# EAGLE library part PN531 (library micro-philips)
Near Field Communication Transmission module Source: http://www.semiconductors.philips.com/acrobat_download/other/identification/sfs_pn531_rev2.0.pdf
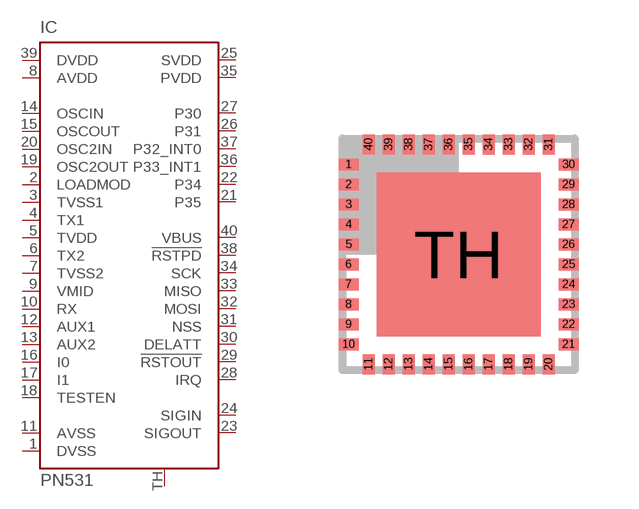
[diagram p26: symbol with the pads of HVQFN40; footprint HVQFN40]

Designator prefix IC

## PN531 (MPN: PN5310A3HN/C203,51; OC_FARNELL: unknown; OC_NEWARK: 70R7886)  [HVQFN40]
1  DVSS  pwr
2  LOADMOD  out
3  TVSS1  pwr
4  TX1  out
5  TVDD  pwr
6  TX2  out
7  TVSS2  pwr
8  AVDD  pwr
9  VMID  pwr
10  RX  in
11  AVSS  pwr
12  AUX1  out
13  AUX2  out
14  OSCIN  in
15  OSCOUT  out
16  I0  in
17  I1  in
18  TESTEN  in
19  OSC2OUT  out
20  OSC2IN  in
21  P35
22  P34
23  SIGOUT  out
24  SIGIN  in
25  SVDD  pwr
26  P31
27  P30
28  IRQ  out
29  !RSTOUT
30  DELATT  out
31  NSS
32  MOSI
33  MISO
34  SCK
35  PVDD  pwr
36  P33_INT1
37  P32_INT0
38  !RSTPD  in
39  DVDD  in
40  VBUS  in
TH  TH  pas

## Footprint HVQFN40 (pad centres in mm)
HVQFN40 plastic thermal enhanced very thin quad flat package SOT618-1 no leads; 40 terminals; body 6 x 6 x 0.85 mm Source: http://www.semiconductors.philips.com/acrobat_download/packages/SOT618-1.pdf
smd 0.5 x 0.3: 1 -2.75,2.25; 2 -2.75,1.75; 3 -2.75,1.25; 4 -2.75,0.75; 5 -2.75,0.25; 6 -2.75,-0.25; 7 -2.75,-0.75; 8 -2.75,-1.25; 9 -2.75,-1.75; 10 -2.75,-2.25; 21 2.75,-2.25; 22 2.75,-1.75; 23 2.75,-1.25; 24 2.75,-0.75; 25 2.75,-0.25; 26 2.75,0.25; 27 2.75,0.75; 28 2.75,1.25; 29 2.75,1.75; 30 2.75,2.25
smd 0.3 x 0.5: 11 -2.25,-2.75; 12 -1.75,-2.75; 13 -1.25,-2.75; 14 -0.75,-2.75; 15 -0.25,-2.75; 16 0.25,-2.75; 17 0.75,-2.75; 18 1.25,-2.75; 19 1.75,-2.75; 20 2.25,-2.75; 31 2.25,2.75; 32 1.75,2.75; 33 1.25,2.75; 34 0.75,2.75; 35 0.25,2.75; 36 -0.25,2.75; 37 -0.75,2.75; 38 -1.25,2.75; 39 -1.75,2.75; 40 -2.25,2.75
smd 4.1 x 4.1: TH 0,0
